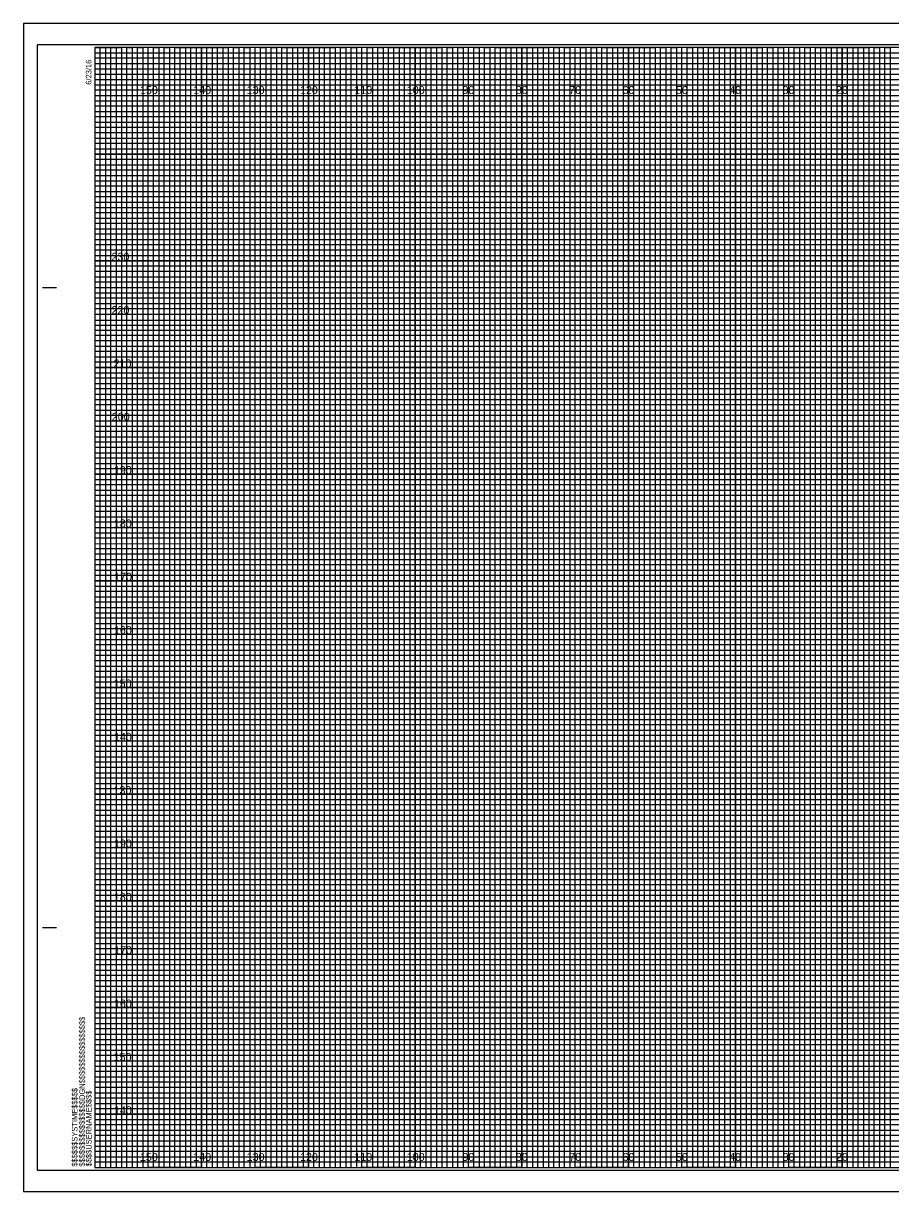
# Model space of a CAD drawing. Extents: x -13 to 323, y -5 to 1754.
# Drawn here: x -13.4 to 149.1, y 875.5 to 1094.5 of the extents above; entities that cross this region are included whole.
import ezdxf

# ---------------------------------------------------------------- set-up
doc = ezdxf.new("R2010")
doc.units = 0
for name, color, linetype in [('Exist Cross Section Cell', 7, 'Continuous'), ('Exist XS Center Line Elevation Label', 7, 'Continuous'), ('Exist XS Ground Line', 7, 'Continuous'), ('Prop CMT Pvmt Course 1', 7, 'Continuous'), ('Prop CMT Pvmt Course 2', 7, 'Continuous'), ('Prop CMT Pvmt Course 3', 7, 'Continuous'), ('Prop CMT Shld Paved Course 1', 7, 'Continuous'), ('Prop CMT Shld Paved Course 2', 7, 'Continuous'), ('Prop CMT Subgrade Earthwork', 7, 'Continuous'), ('Prop XS Ditch Standard Text', 7, 'Continuous'), ('Scratch_Level_0', 7, 'Continuous')]:
    doc.layers.add(name, color=color, linetype=linetype)

msp = doc.modelspace()

# ---------------------------------------------------------------- linework, layer by layer
at = {"layer": 'Exist XS Center Line Elevation Label'}
for points in [[(0, 1090), (5, 1090), (5, 880), (15, 880), (15, 1090), (25, 1090), (25, 880), (35, 880), (35, 1090), (45, 1090), (45, 880), (55, 880), (55, 1090), (65, 1090), (65, 880), (75, 880), (75, 1090), (85, 1090), (85, 880), (95, 880), (95, 1090), (105, 1090), (105, 880), (115, 880), (115, 1090), (125, 1090), (125, 880), (135, 880), (135, 1090), (145, 1090), (145, 880), (155, 880)], [(0, 1085), (275, 1085)], [(0, 1065), (320, 1065), (320, 1075), (0, 1075)], [(0, 1045), (320, 1045), (320, 1055), (0, 1055)], [(0, 1025), (320, 1025), (320, 1035), (0, 1035)], [(0, 1005), (320, 1005), (320, 1015), (0, 1015)], [(0, 985), (320, 985), (320, 995), (0, 995)], [(0, 965), (320, 965), (320, 975), (0, 975)], [(0, 945), (320, 945), (320, 955), (0, 955)], [(0, 925), (320, 925), (320, 935), (0, 935)], [(0, 905), (320, 905), (320, 915), (0, 915)], [(0, 885), (320, 885), (320, 895), (0, 895)]]:
    msp.add_lwpolyline(points, dxfattribs=at)
at = {"layer": 'Exist XS Ground Line'}
for p, q in [((10, 1090), (0, 1090)), ((10, 880), (10, 1090)), ((30, 1090), (20, 1090)), ((20, 1090), (20, 880)), ((30, 880), (30, 1090)), ((50, 1090), (40, 1090)), ((40, 1090), (40, 880)), ((50, 880), (50, 1090)), ((70, 1090), (60, 1090)), ((60, 1090), (60, 880)), ((70, 880), (70, 1090)), ((90, 1090), (80, 1090)), ((80, 1090), (80, 880)), ((90, 880), (90, 1090)), ((110, 1090), (100, 1090)), ((100, 1090), (100, 880)), ((110, 880), (110, 1090)), ((130, 1090), (120, 1090)), ((120, 1090), (120, 880)), ((130, 880), (130, 1090)), ((150, 1090), (140, 1090)), ((140, 1090), (140, 880)), ((20, 880), (10, 880)), ((40, 880), (30, 880)), ((60, 880), (50, 880)), ((80, 880), (70, 880)), ((100, 880), (90, 880)), ((120, 880), (110, 880)), ((140, 880), (130, 880))]:
    msp.add_line(p, q, dxfattribs=at)
for points in [[(0, 1080), (320, 1080), (320, 1070), (0, 1070)], [(0, 1060), (320, 1060), (320, 1050), (0, 1050)], [(0, 1040), (320, 1040), (320, 1030), (0, 1030)], [(0, 1020), (320, 1020), (320, 1010), (0, 1010)], [(0, 1000), (320, 1000), (320, 990), (0, 990)], [(0, 980), (320, 980), (320, 970), (0, 970)], [(0, 960), (320, 960), (320, 950), (0, 950)], [(0, 940), (320, 940), (320, 930), (0, 930)], [(0, 920), (320, 920), (320, 910), (0, 910)], [(0, 900), (320, 900), (320, 890), (0, 890)]]:
    msp.add_lwpolyline(points, dxfattribs=at)
at = {"layer": 'Prop CMT Pvmt Course 1'}
for p, q in [((323.3, 1094.5), (-13.4, 1094.5)), ((-13.4, 1094.5), (-13.4, 875.5)), ((-13.4, 875.5), (323.3, 875.5))]:
    msp.add_line(p, q, dxfattribs=at)
at = {"layer": 'Prop CMT Pvmt Course 2'}
msp.add_lwpolyline([(-13.4, 875.5), (323.3, 875.5), (323.3, 1094.5), (-13.4, 1094.5)], close=True, dxfattribs=at)
at = {"layer": 'Prop CMT Pvmt Course 3'}
msp.add_lwpolyline([(-10.8, 879.5), (322.4, 879.5), (322.4, 1090.5), (-10.8, 1090.5)], close=True, dxfattribs=at)
at = {"layer": 'Prop CMT Shld Paved Course 1'}
for p, q in [((-9.8, 1045), (-7.3, 1045)), ((-9.7, 1045), (-7.2, 1045)), ((-9.8, 925), (-7.3, 925)), ((-9.7, 925), (-7.2, 925)), ((0, 880), (0, 880)), ((0, 880), (0, 880)), ((0, 880), (0, 880)), ((0, 880), (0, 880)), ((0, 880), (0, 880)), ((0, 880), (0, 880)), ((0, 880), (0, 880))]:
    msp.add_line(p, q, dxfattribs=at)
msp.add_lwpolyline([(320, 1090), (0, 1090), (0, 880), (320, 880)], close=True, dxfattribs=at)
at = {"layer": 'Prop CMT Shld Paved Course 2'}
for points in [[(0, 880), (1, 880), (1, 1090), (2, 1090), (2, 880)], [(2, 880), (3, 880), (3, 1090), (4, 1090), (4, 880)], [(5, 880), (6, 880), (6, 1090), (7, 1090), (7, 880)], [(7, 880), (8, 880), (8, 1090), (9, 1090), (9, 880)], [(10, 880), (11, 880), (11, 1090), (12, 1090), (12, 880)], [(12, 880), (13, 880), (13, 1090), (14, 1090), (14, 880)], [(15, 880), (16, 880), (16, 1090), (17, 1090), (17, 880)], [(17, 880), (18, 880), (18, 1090), (19, 1090), (19, 880)], [(20, 880), (21, 880), (21, 1090), (22, 1090), (22, 880)], [(22, 880), (23, 880), (23, 1090), (24, 1090), (24, 880)], [(25, 880), (26, 880), (26, 1090), (27, 1090), (27, 880)], [(27, 880), (28, 880), (28, 1090), (29, 1090), (29, 880)], [(30, 880), (31, 880), (31, 1090), (32, 1090), (32, 880)], [(32, 880), (33, 880), (33, 1090), (34, 1090), (34, 880)], [(35, 880), (36, 880), (36, 1090), (37, 1090), (37, 880)], [(37, 880), (38, 880), (38, 1090), (39, 1090), (39, 880)], [(40, 880), (41, 880), (41, 1090), (42, 1090), (42, 880)], [(42, 880), (43, 880), (43, 1090), (44, 1090), (44, 880)], [(45, 880), (46, 880), (46, 1090), (47, 1090), (47, 880)], [(47, 880), (48, 880), (48, 1090), (49, 1090), (49, 880)], [(50, 880), (51, 880), (51, 1090), (52, 1090), (52, 880)], [(52, 880), (53, 880), (53, 1090), (54, 1090), (54, 880)], [(55, 880), (56, 880), (56, 1090), (57, 1090), (57, 880)], [(57, 880), (58, 880), (58, 1090), (59, 1090), (59, 880)], [(60, 880), (61, 880), (61, 1090), (62, 1090), (62, 880)], [(62, 880), (63, 880), (63, 1090), (64, 1090), (64, 880)], [(65, 880), (66, 880), (66, 1090), (67, 1090), (67, 880)], [(67, 880), (68, 880), (68, 1090), (69, 1090), (69, 880)], [(70, 880), (71, 880), (71, 1090), (72, 1090), (72, 880)], [(72, 880), (73, 880), (73, 1090), (74, 1090), (74, 880)], [(75, 880), (76, 880), (76, 1090), (77, 1090), (77, 880)], [(77, 880), (78, 880), (78, 1090), (79, 1090), (79, 880)], [(80, 880), (81, 880), (81, 1090), (82, 1090), (82, 880)], [(82, 880), (83, 880), (83, 1090), (84, 1090), (84, 880)], [(85, 880), (86, 880), (86, 1090), (87, 1090), (87, 880)], [(87, 880), (88, 880), (88, 1090), (89, 1090), (89, 880)], [(90, 880), (91, 880), (91, 1090), (92, 1090), (92, 880)], [(92, 880), (93, 880), (93, 1090), (94, 1090), (94, 880)], [(95, 880), (96, 880), (96, 1090), (97, 1090), (97, 880)], [(97, 880), (98, 880), (98, 1090), (99, 1090), (99, 880)], [(100, 880), (101, 880), (101, 1090), (102, 1090), (102, 880)], [(102, 880), (103, 880), (103, 1090), (104, 1090), (104, 880)], [(105, 880), (106, 880), (106, 1090), (107, 1090), (107, 880)], [(107, 880), (108, 880), (108, 1090), (109, 1090), (109, 880)], [(110, 880), (111, 880), (111, 1090), (112, 1090), (112, 880)], [(112, 880), (113, 880), (113, 1090), (114, 1090), (114, 880)], [(115, 880), (116, 880), (116, 1090), (117, 1090), (117, 880)], [(117, 880), (118, 880), (118, 1090), (119, 1090), (119, 880)], [(120, 880), (121, 880), (121, 1090), (122, 1090), (122, 880)], [(122, 880), (123, 880), (123, 1090), (124, 1090), (124, 880)], [(125, 880), (126, 880), (126, 1090), (127, 1090), (127, 880)], [(127, 880), (128, 880), (128, 1090), (129, 1090), (129, 880)], [(130, 880), (131, 880), (131, 1090), (132, 1090), (132, 880)], [(132, 880), (133, 880), (133, 1090), (134, 1090), (134, 880)], [(135, 880), (136, 880), (136, 1090), (137, 1090), (137, 880)], [(137, 880), (138, 880), (138, 1090), (139, 1090), (139, 880)], [(140, 880), (141, 880), (141, 1090), (142, 1090), (142, 880)], [(142, 880), (143, 880), (143, 1090), (144, 1090), (144, 880)], [(145, 880), (146, 880), (146, 1090), (147, 1090), (147, 880)], [(147, 880), (148, 880), (148, 1090), (149, 1090), (149, 880)]]:
    msp.add_lwpolyline(points, dxfattribs=at)
at = {"layer": 'Prop CMT Subgrade Earthwork'}
for p, q in [((10, 880), (10, 1090)), ((20, 880), (20, 1090)), ((30, 880), (30, 1090)), ((40, 880), (40, 1090)), ((50, 880), (50, 1090)), ((60, 880), (60, 1090)), ((70, 880), (70, 1090)), ((80, 880), (80, 1090)), ((90, 880), (90, 1090)), ((100, 880), (100, 1090)), ((110, 880), (110, 1090)), ((120, 880), (120, 1090)), ((130, 880), (130, 1090)), ((140, 880), (140, 1090)), ((0, 1080), (320, 1080)), ((0, 1070), (320, 1070)), ((0, 1060), (320, 1060)), ((0, 1050), (320, 1050)), ((0, 1040), (320, 1040)), ((0, 1030), (320, 1030)), ((0, 1020), (320, 1020)), ((0, 1010), (320, 1010)), ((0, 1000), (320, 1000)), ((0, 990), (320, 990)), ((0, 980), (320, 980)), ((0, 970), (320, 970)), ((0, 960), (320, 960)), ((0, 950), (320, 950)), ((0, 940), (320, 940)), ((0, 930), (320, 930)), ((0, 920), (320, 920)), ((0, 910), (320, 910)), ((0, 900), (320, 900)), ((0, 890), (320, 890))]:
    msp.add_line(p, q, dxfattribs=at)
at = {"layer": 'Scratch_Level_0'}
for p, q in [((0, 1089), (260, 1089)), ((260, 1087.98), (0, 1087.98)), ((0, 1087.98), (0, 1087)), ((0, 1087), (260, 1087)), ((260, 1085.89), (0, 1085.89)), ((0, 1085.89), (0, 1084)), ((0, 1084), (320, 1084))]:
    msp.add_line(p, q, dxfattribs=at)
for points in [[(0, 1083), (270, 1083), (320, 1083), (320, 1082), (0, 1082)], [(0, 1081), (320, 1081), (320, 1079), (0, 1079)], [(0, 1078), (320, 1078), (320, 1077), (0, 1076.98)], [(0, 1076), (320, 1076), (320, 1074), (0, 1074)], [(0, 1073), (320, 1073), (320, 1072), (0, 1072)], [(0, 1071), (320, 1071), (320, 1069), (0, 1069)], [(0, 1068), (320, 1068), (320, 1067), (0, 1067)], [(0, 1066), (320, 1066), (320, 1064), (0, 1064)], [(0, 1063), (320, 1063), (320, 1062), (0, 1062)], [(0, 1061), (320, 1061), (320, 1059), (0, 1059)], [(0, 1058), (320, 1058), (320, 1057), (0, 1057)], [(0, 1056), (320, 1056), (320, 1053.95), (320, 1053), (320, 1052), (0, 1052)], [(0, 1054), (320, 1054), (320, 1053), (0, 1053)], [(0, 1051), (320, 1051), (320, 1049), (0, 1049.03)], [(0, 1049.03), (320, 1049), (320, 1048), (0, 1048)], [(0, 1047), (320, 1047), (320, 1046), (0, 1046)], [(0, 1044), (320, 1044), (320, 1043), (0, 1043)], [(0, 1042), (320, 1042), (320, 1041), (0, 1041)], [(-0.07, 1038.89), (320, 1038.89), (320, 1037.88), (-0.07, 1037.88)], [(0, 1037), (320, 1037), (320, 1036), (0, 1036)], [(0, 1034), (320, 1034), (320, 1033), (0, 1033)], [(0, 1032), (320, 1032), (320, 1031), (0, 1031)], [(0, 1029), (320, 1029), (320, 1028), (0, 1028)], [(0, 1027), (320, 1027), (320, 1026), (0, 1026)], [(0, 1024), (320, 1024), (320, 1023), (0, 1023)], [(0, 1022), (320, 1022), (320, 1021), (0, 1021)], [(0, 1019), (320, 1019), (319.99, 1017.98), (0, 1018)], [(0, 1017), (320, 1017), (320, 1016), (0, 1016)], [(0, 1014), (320, 1014), (320, 1013), (0, 1013)], [(0, 1012), (320, 1012), (320, 1011), (0, 1011)], [(0, 1009), (320, 1009), (320, 1008), (0, 1008)], [(0, 1007), (320, 1007), (320, 1006), (0, 1006)], [(0, 1004), (320, 1004), (320, 1003), (0, 1003)], [(0, 1002), (320, 1002), (320, 1001), (0, 1001)], [(0, 999), (320, 999), (320, 998), (0, 998)], [(0, 996.99), (320.07, 996.91), (320, 996), (0, 996)], [(0, 994), (320, 994), (320, 993), (0, 993)], [(0, 992), (320, 992), (320, 991), (0, 991)], [(0, 989), (320, 989), (320, 988), (0, 988)], [(0, 987), (320, 987), (320, 986), (0, 986)], [(0, 984), (320, 984), (320, 983), (0, 983)], [(0, 982), (320, 982), (320, 981), (0, 981)], [(0, 979), (320, 979), (320, 978), (0, 978)], [(0, 977), (320, 977), (320, 976), (0, 976)], [(0, 974), (320, 974), (320, 973), (0, 973)], [(0, 972), (320, 972), (320, 971), (0, 971)], [(0, 969), (320, 969), (320, 968), (0, 968)], [(0, 967), (320, 967), (320, 966), (0, 966)], [(0, 964), (320, 964), (320, 963), (0, 963)], [(0, 962), (320, 962), (320, 961), (0, 961)], [(0, 959), (320, 959), (319.99, 957.98), (0, 958)], [(0, 957), (320, 957), (320, 956), (0, 956)], [(0, 954), (320, 954), (320, 953), (0, 953)], [(0, 952), (320, 952), (320, 951), (0, 951)], [(0, 949), (320, 949), (320, 948), (0, 948)], [(0, 947), (320, 947), (320, 946), (0, 946)], [(0, 944), (320, 944), (320, 943), (0, 943)], [(0, 942), (320, 942), (320, 941), (0, 941)], [(0, 939), (320, 939), (320, 938), (0, 938)], [(0, 936.99), (320.07, 936.91), (320, 936), (0, 936)], [(0, 934), (320, 934), (320, 933), (0, 933)], [(0, 932), (320, 932), (320, 931), (0, 931)], [(0, 929), (320, 929), (320, 928), (0, 928)], [(0, 927), (320, 927), (320, 926), (0, 926)], [(0, 924), (320, 924), (320, 923), (0, 923)], [(0, 922), (320, 922), (320, 921), (0, 921)], [(0, 919), (320, 919), (320, 918), (0, 918)], [(0, 917), (320, 917), (320, 916), (0, 916)], [(0, 914), (320, 914), (320, 913), (0, 913)], [(0, 912), (320, 912), (320, 911), (0, 911)], [(0, 909), (320, 909), (320, 908), (0, 908)], [(0, 907), (320, 907), (320, 906), (0, 906)], [(0, 904), (320, 904), (320, 903), (0, 903)], [(0, 902), (320, 902), (320, 901), (0, 901)], [(0, 899), (320, 899), (320, 898), (0, 898)], [(0, 897), (320, 897), (320, 896), (0, 896)], [(0, 894), (320, 894), (320, 893), (0, 893)], [(0, 892), (320, 892), (320, 891), (0, 891)], [(0, 889), (320, 889), (320, 888), (0, 888)], [(0, 887), (320, 887), (320, 886), (0, 886)], [(0, 884), (320, 884), (320, 883), (0, 883)], [(0, 882), (320, 882), (320, 881), (0, 881)]]:
    msp.add_lwpolyline(points, dxfattribs=at)

# ---------------------------------------------------------------- texts
at = {"layer": 'Exist Cross Section Cell'}
for s, p in [('230', (3.11, 1050)), ('220', (3.12, 1040)), ('210', (3.5, 1030)), ('200', (3.17, 1020)), ('190', (3.57, 1010)), ('180', (3.55, 1000)), ('170', (3.61, 990)), ('160', (3.57, 980)), ('150', (3.52, 970)), ('140', (3.57, 960)), ('130', (3.49, 950)), ('190', (3.57, 940)), ('180', (3.55, 930)), ('170', (3.61, 920)), ('160', (3.57, 910)), ('150', (3.52, 900)), ('140', (3.57, 890))]:
    msp.add_text(s, height=1.5, dxfattribs=at).set_placement(p)
at = {"layer": 'Prop CMT Shld Paved Course 1'}
for s, p in [('6/23/16', (-0.65, 1083)), ('$$$$$$$$$$$$$$$$DGN$$$$$$$$$$$$$$$$', (-1.88, 880.18)), ('$$$$$$SYSTIME$$$$$', (-3.26, 880.18)), ('$$$$USERNAME$$$$', (-0.62, 880.23))]:
    msp.add_text(s, height=1.05, rotation=90, dxfattribs=at).set_placement(p)
at = {"layer": 'Prop XS Ditch Standard Text'}
for s, p in [('150', (8.44, 1081.25)), ('140', (18.44, 1081.25)), ('130', (28.44, 1081.25)), ('120', (38.44, 1081.25)), ('110', (48.62, 1081.25)), ('100', (58.44, 1081.25)), ('90', (68.86, 1081.25)), ('80', (78.86, 1081.25)), ('70', (88.86, 1081.25)), ('60', (98.86, 1081.25)), ('50', (108.86, 1081.25)), ('40', (118.86, 1081.25)), ('30', (128.86, 1081.25)), ('20', (138.86, 1081.25)), ('150', (8.44, 881.25)), ('140', (18.44, 881.25)), ('130', (28.44, 881.25)), ('120', (38.44, 881.25)), ('110', (48.62, 881.25)), ('100', (58.44, 881.25)), ('90', (68.86, 881.25)), ('80', (78.86, 881.25)), ('70', (88.86, 881.25)), ('60', (98.86, 881.25)), ('50', (108.86, 881.25)), ('40', (118.86, 881.25)), ('30', (128.86, 881.25)), ('20', (138.86, 881.25))]:
    msp.add_text(s, height=1.5, dxfattribs=at).set_placement(p)

doc.saveas('drawing.dxf')
